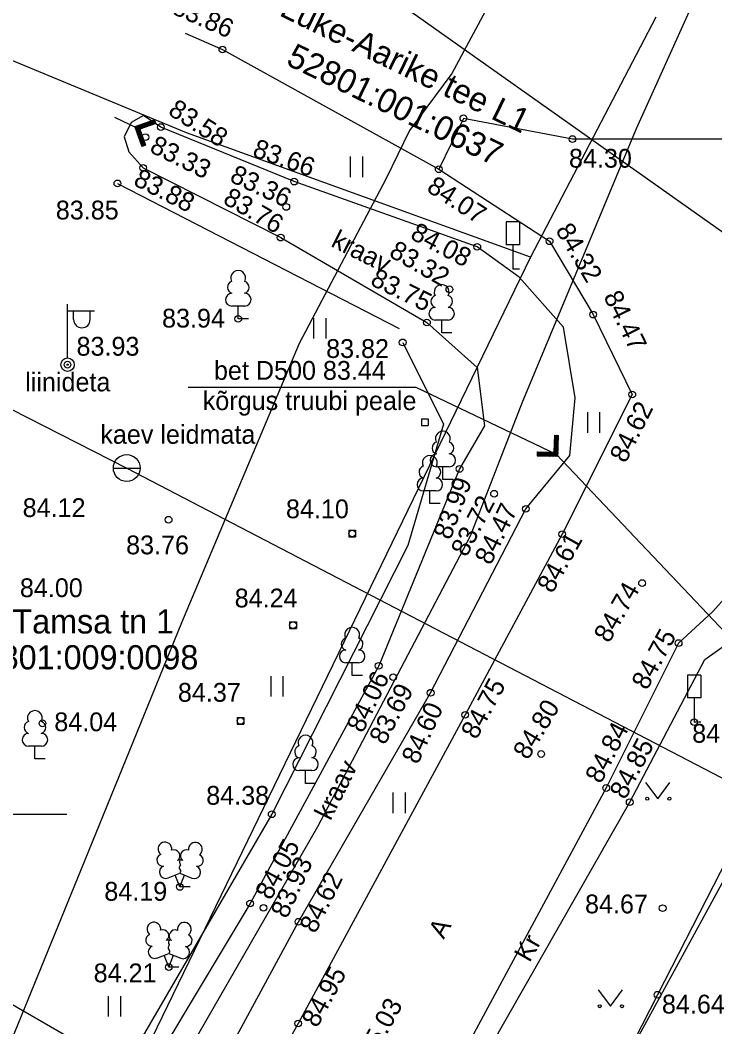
# Model space of a CAD drawing. Extents: x 648748 to 649126, y 6457789 to 6458252.
# Drawn here: x 648900.26 to 648926.14, y 6458192.08 to 6458229.55 of the extents above; entities that cross this region are included whole.
import ezdxf

# ---------------------------------------------------------------- set-up
doc = ezdxf.new("R2010")
doc.units = 0
for name, color, linetype in [('AED', 7, 'Continuous'), ('HALJASTUS', 7, 'Continuous'), ('KORGUS-EH2000', 7, 'Continuous'), ('LIIKLUS', 7, 'Continuous'), ('PIIR', 7, 'Continuous'), ('POST', 7, 'Continuous'), ('PUU', 7, 'Continuous'), ('SITRASS', 7, 'Continuous'), ('TEE', 7, 'Continuous'), ('TRUUP', 7, 'Continuous'), ('VEEKOGU', 7, 'Continuous'), ('VKAEV', 7, 'Continuous'), ('VORK', 7, 'Continuous'), ('VTRASS', 7, 'Continuous')]:
    doc.layers.add(name, color=color, linetype=linetype)

msp = doc.modelspace()

# ---------------------------------------------------------------- linework, layer by layer
at = {"layer": 'AED'}
for p, q in [((648915.208, 6458214.709), (648915.208, 6458214.459)), ((648915.208, 6458214.709), (648915.458, 6458214.709)), ((648915.208, 6458214.459), (648915.458, 6458214.459)), ((648915.458, 6458214.709), (648915.458, 6458214.459)), ((648912.5, 6458210.569), (648912.5, 6458210.319)), ((648912.5, 6458210.569), (648912.75, 6458210.569)), ((648912.5, 6458210.319), (648912.75, 6458210.319)), ((648912.75, 6458210.569), (648912.75, 6458210.319)), ((648910.297, 6458207.157), (648910.297, 6458206.907)), ((648910.297, 6458207.157), (648910.547, 6458207.157)), ((648910.547, 6458207.157), (648910.547, 6458206.907)), ((648910.297, 6458206.907), (648910.547, 6458206.907)), ((648908.343, 6458203.593), (648908.343, 6458203.343)), ((648908.343, 6458203.593), (648908.593, 6458203.593)), ((648908.593, 6458203.593), (648908.593, 6458203.343)), ((648908.343, 6458203.343), (648908.593, 6458203.343))]:
    msp.add_line(p, q, dxfattribs=at)
msp.add_lwpolyline([(648940.464, 6458193.018), (648933.165, 6458198.026), (648928.158, 6458201.393), (648924, 6458193.279), (648918.475, 6458182.472), (648914.302, 6458174.583), (648912.702, 6458171.37), (648918.536, 6458167.903)], dxfattribs=at)
at = {"layer": 'HALJASTUS'}
for p, q in [((648912.551, 6458224.472), (648912.551, 6458223.711)), ((648913.006, 6458224.472), (648913.006, 6458223.711)), ((648911.185, 6458218.458), (648911.185, 6458217.697)), ((648911.64, 6458218.458), (648911.64, 6458217.697)), ((648921.388, 6458214.956), (648921.388, 6458214.195)), ((648921.843, 6458214.956), (648921.843, 6458214.195)), ((648909.593, 6458205.137), (648909.593, 6458204.376)), ((648910.048, 6458205.137), (648910.048, 6458204.376)), ((648923.553, 6458201.182), (648924.016, 6458200.575)), ((648924.016, 6458200.575), (648924.462, 6458201.182)), ((648914.14, 6458200.802), (648914.14, 6458200.041)), ((648914.595, 6458200.802), (648914.595, 6458200.041)), ((648921.785, 6458193.457), (648922.248, 6458192.851)), ((648922.248, 6458192.851), (648922.694, 6458193.457)), ((648903.543, 6458193.224), (648903.543, 6458192.463)), ((648903.998, 6458193.224), (648903.998, 6458192.463))]:
    msp.add_line(p, q, dxfattribs=at)
msp.add_lwpolyline([(648914.508, 6458217.558), (648916.03, 6458214.515), (648914.704, 6458209.998), (648909.63, 6458199.994), (648897.923, 6458179.895)], dxfattribs=at)
for centre in [(648923.615, 6458200.575), (648924.444, 6458200.575), (648921.847, 6458192.851), (648922.676, 6458192.851)]:
    msp.add_circle(centre, 0.055, dxfattribs=at)
at = {"layer": 'KORGUS-EH2000'}
for centre in [(648907.793, 6458228.458), (648905.502, 6458225.572), (648916.77, 6458225.896), (648904.924, 6458225.198), (648920.831, 6458225.126), (648904.843, 6458224.054), (648915.851, 6458224.001), (648903.883, 6458223.474), (648910.47, 6458223.541), (648910.173, 6458222.6), (648909.964, 6458221.457), (648917.286, 6458221.114), (648919.979, 6458221.321), (648916.247, 6458219.532), (648908.384, 6458218.435), (648921.601, 6458218.591), (648915.412, 6458218.298), (648914.508, 6458217.558), (648902.026, 6458216.728), (648923.058, 6458215.616), (648916.627, 6458212.847), (648917.911, 6458211.924), (648919.095, 6458211.362), (648905.79, 6458210.957), (648912.625, 6458210.444), (648920.447, 6458210.418), (648923.423, 6458208.6), (648910.422, 6458207.032), (648924.786, 6458206.368), (648913.614, 6458205.518), (648914.152, 6458205.1), (648915.55, 6458204.519), (648908.468, 6458203.468), (648916.834, 6458203.698), (648901.093, 6458203.379), (648925.367, 6458203.425), (648919.666, 6458202.237), (648922.091, 6458200.973), (648922.963, 6458200.444), (648909.63, 6458199.994), (648906.207, 6458197.289), (648908.824, 6458196.674), (648909.326, 6458196.511), (648924.191, 6458196.5), (648910.629, 6458195.996), (648905.796, 6458194.307), (648924, 6458193.279), (648910.613, 6458192.21)]:
    msp.add_circle(centre, 0.125, dxfattribs=at)
at = {"layer": 'LIIKLUS'}
for points in [[(648918.364, 6458222.039), (648918.364, 6458221.189)], [(648918.864, 6458222.039), (648918.364, 6458222.039)], [(648918.864, 6458222.039), (648918.864, 6458221.189)], [(648918.864, 6458221.189), (648918.364, 6458221.189)], [(648918.614, 6458221.189), (648918.614, 6458220.289)], [(648918.864, 6458220.289), (648918.614, 6458220.289)], [(648925.117, 6458205.175), (648925.117, 6458204.325)], [(648925.617, 6458205.175), (648925.117, 6458205.175)], [(648925.617, 6458205.175), (648925.617, 6458204.325)], [(648925.617, 6458204.325), (648925.117, 6458204.325)], [(648925.367, 6458204.325), (648925.367, 6458203.425)], [(648925.617, 6458203.425), (648925.367, 6458203.425)]]:
    msp.add_lwpolyline(points, dxfattribs=at)
at = {"layer": 'PIIR'}
for p, q in [((648906.45, 6458225.36), (648896.582, 6458229.443)), ((648923.94, 6458229.66), (648919.27, 6458220.73)), ((648919.27, 6458220.73), (648906.45, 6458225.36)), ((648919.27, 6458220.73), (648904.5, 6458190.31)), ((648911.52, 6458170.14), (648929.78, 6458203.63)), ((648882.169, 6458203.173), (648904.5, 6458190.31))]:
    msp.add_line(p, q, dxfattribs=at)
at = {"layer": 'POST'}
for p, q in [((648902.026, 6458216.978), (648902.026, 6458218.978)), ((648902.026, 6458218.728), (648903.026, 6458218.728)), ((648902.252, 6458218.406), (648902.252, 6458218.728)), ((648902.865, 6458218.406), (648902.865, 6458218.728))]:
    msp.add_line(p, q, dxfattribs=at)
for radius in [0.25, 0.0234]:
    msp.add_circle((648902.026, 6458216.728), radius, dxfattribs=at)
msp.add_arc((648902.559, 6458218.406), 0.306, 180, 0, dxfattribs=at)
at = {"layer": 'PUU'}
for p, q in [((648903.883, 6458223.474), (648914.375, 6458218.079)), ((648908.624, 6458218.91), (648908.144, 6458218.91)), ((648908.384, 6458218.435), (648908.384, 6458218.91)), ((648908.764, 6458218.435), (648908.384, 6458218.435)), ((648916.201, 6458218.387), (648915.721, 6458218.387)), ((648915.961, 6458217.912), (648915.961, 6458218.387)), ((648916.341, 6458217.912), (648915.961, 6458217.912)), ((648916.245, 6458212.932), (648915.765, 6458212.932)), ((648916.005, 6458212.457), (648916.005, 6458212.932)), ((648916.385, 6458212.457), (648916.005, 6458212.457)), ((648915.76, 6458212.03), (648915.28, 6458212.03)), ((648915.52, 6458211.555), (648915.52, 6458212.03)), ((648915.9, 6458211.555), (648915.52, 6458211.555)), ((648912.865, 6458205.633), (648912.385, 6458205.633)), ((648912.625, 6458205.158), (648912.625, 6458205.633)), ((648913.005, 6458205.158), (648912.625, 6458205.158)), ((648901.051, 6458202.529), (648900.571, 6458202.529)), ((648900.811, 6458202.054), (648900.811, 6458202.529)), ((648901.191, 6458202.054), (648900.811, 6458202.054)), ((648911.128, 6458201.619), (648910.648, 6458201.619)), ((648910.888, 6458201.144), (648910.888, 6458201.619)), ((648911.268, 6458201.144), (648910.888, 6458201.144)), ((648905.767, 6458197.624), (648906.212, 6458197.799)), ((648906.207, 6458197.289), (648906.032, 6458197.729)), ((648906.207, 6458197.289), (648906.387, 6458197.729)), ((648906.212, 6458197.799), (648906.652, 6458197.619)), ((648906.587, 6458197.289), (648906.207, 6458197.289)), ((648905.356, 6458194.642), (648905.801, 6458194.817)), ((648905.796, 6458194.307), (648905.621, 6458194.747)), ((648905.796, 6458194.307), (648905.976, 6458194.747)), ((648905.801, 6458194.817), (648906.241, 6458194.637)), ((648906.176, 6458194.307), (648905.796, 6458194.307))]:
    msp.add_line(p, q, dxfattribs=at)
for points in [[(648906.212, 6458198.294), (648906.192, 6458198.219), (648906.192, 6458198.199), (648906.202, 6458198.169), (648906.222, 6458198.134), (648906.227, 6458198.114), (648906.212, 6458198.079), (648906.187, 6458198.029), (648906.182, 6458198.004), (648906.187, 6458197.989), (648906.197, 6458197.959), (648906.232, 6458197.899), (648906.237, 6458197.879), (648906.232, 6458197.859), (648906.217, 6458197.824), (648906.212, 6458197.799)], [(648905.801, 6458195.312), (648905.781, 6458195.237), (648905.781, 6458195.217), (648905.791, 6458195.187), (648905.811, 6458195.152), (648905.816, 6458195.132), (648905.801, 6458195.097), (648905.776, 6458195.047), (648905.771, 6458195.022), (648905.776, 6458195.007), (648905.786, 6458194.977), (648905.821, 6458194.917), (648905.826, 6458194.897), (648905.821, 6458194.877), (648905.806, 6458194.842), (648905.801, 6458194.817)]]:
    msp.add_lwpolyline(points, dxfattribs=at)
for centre, radius, start, end in [((648908.384, 6458219.955), 0.277, 332.58, 207.42), ((648908.214, 6458219.608), 0.233, 109.022, 253.142), ((648908.554, 6458219.608), 0.233, 286.851, 70.986), ((648915.961, 6458219.432), 0.277, 332.58, 207.42), ((648908.146, 6458219.148), 0.238, 90.002, 269.395), ((648908.621, 6458219.148), 0.238, 270.605, 89.998), ((648915.791, 6458219.084), 0.233, 109.022, 253.142), ((648916.131, 6458219.084), 0.233, 286.851, 70.986), ((648915.724, 6458218.624), 0.238, 90.002, 269.395), ((648916.199, 6458218.624), 0.238, 270.605, 89.998), ((648916.005, 6458213.977), 0.277, 332.58, 207.42), ((648915.835, 6458213.629), 0.233, 109.022, 253.142), ((648916.175, 6458213.629), 0.233, 286.851, 70.986), ((648915.52, 6458213.075), 0.277, 332.58, 207.42), ((648915.767, 6458213.169), 0.238, 90.002, 269.395), ((648916.242, 6458213.169), 0.238, 270.605, 89.998), ((648915.35, 6458212.727), 0.233, 109.022, 253.142), ((648915.69, 6458212.727), 0.233, 286.851, 70.986), ((648915.282, 6458212.267), 0.238, 90.002, 269.395), ((648915.757, 6458212.267), 0.238, 270.605, 89.998), ((648912.625, 6458206.678), 0.277, 332.58, 207.42), ((648912.455, 6458206.33), 0.233, 109.022, 253.142), ((648912.795, 6458206.33), 0.233, 286.851, 70.986), ((648912.388, 6458205.87), 0.238, 90.002, 269.395), ((648912.863, 6458205.87), 0.238, 270.605, 89.998), ((648900.811, 6458203.574), 0.277, 332.58, 207.42), ((648900.641, 6458203.226), 0.233, 109.022, 253.142), ((648900.981, 6458203.226), 0.233, 286.851, 70.986), ((648900.573, 6458202.766), 0.238, 90.002, 269.395), ((648901.048, 6458202.766), 0.238, 270.605, 89.998), ((648910.888, 6458202.664), 0.277, 332.58, 207.42), ((648910.718, 6458202.316), 0.233, 109.022, 253.142), ((648911.058, 6458202.316), 0.233, 286.851, 70.986), ((648910.651, 6458201.856), 0.238, 90.002, 269.395), ((648911.126, 6458201.856), 0.238, 270.605, 89.998), ((648905.65, 6458198.703), 0.256, 111.503, 232.517), ((648905.65, 6458198.703), 0.256, 350.486, 111.5), ((648906.786, 6458198.694), 0.256, 67.617, 188.631), ((648906.786, 6458198.694), 0.256, 306.6, 67.614), ((648905.576, 6458198.291), 0.224, 111.43, 274.499), ((648905.985, 6458198.452), 0.224, 308.504, 111.572), ((648906.448, 6458198.448), 0.225, 67.702, 230.513), ((648906.854, 6458198.282), 0.224, 264.618, 67.687), ((648905.681, 6458197.847), 0.237, 111.501, 291.5), ((648906.211, 6458198.056), 0.237, 66.766, 111.501), ((648906.742, 6458197.839), 0.238, 247.617, 67.616), ((648905.239, 6458195.721), 0.256, 111.503, 232.517), ((648905.239, 6458195.721), 0.256, 350.486, 111.5), ((648905.573, 6458195.471), 0.224, 308.504, 111.572), ((648906.036, 6458195.466), 0.225, 67.702, 230.513), ((648906.375, 6458195.713), 0.256, 67.617, 188.631), ((648906.375, 6458195.713), 0.256, 306.6, 67.614), ((648905.165, 6458195.31), 0.224, 111.43, 274.499), ((648905.8, 6458195.075), 0.237, 66.766, 111.501), ((648906.442, 6458195.3), 0.224, 264.618, 67.687), ((648905.269, 6458194.866), 0.237, 111.501, 291.5), ((648906.331, 6458194.858), 0.238, 247.617, 67.616)]:
    msp.add_arc(centre, radius, start, end, dxfattribs=at)
at = {"layer": 'SITRASS'}
for points in [[(648929.925, 6458240.085), (648929.233, 6458238.833), (648926.729, 6458233.327), (648923.21, 6458225.506), (648918.966, 6458215.361), (648917.027, 6458210.342), (648911.341, 6458199.533), (648902.157, 6458183.584), (648896.992, 6458174.764), (648890.118, 6458163.377), (648888.523, 6458160), (648880.878, 6458146.779), (648876.372, 6458138.998), (648873.186, 6458136.533), (648872.398, 6458135.159), (648870.194, 6458131.921), (648868.778, 6458129.583), (648863.975, 6458121.708)], [(648920.046, 6458238.741), (648918.974, 6458235.501), (648918.374, 6458231.362), (648916.343, 6458227.563), (648914.757, 6458225.445), (648913.89, 6458223.662), (648910.648, 6458217.515), (648906.266, 6458207.122), (648902.537, 6458197.956), (648897.439, 6458185.518), (648896.343, 6458186.017)]]:
    msp.add_lwpolyline(points, dxfattribs=at)
at = {"layer": 'TEE'}
for points in [[(648934.477, 6458237.848), (648927.903, 6458225.118), (648920.831, 6458225.126), (648916.77, 6458225.896), (648915.851, 6458224.001), (648919.979, 6458221.321), (648921.601, 6458218.591), (648923.058, 6458215.616), (648920.447, 6458210.418), (648916.834, 6458203.698), (648910.613, 6458192.21), (648903.667, 6458179.751)], [(648906.412, 6458229.067), (648907.793, 6458228.458), (648915.851, 6458224.001)], [(648891.319, 6458123.494), (648901.175, 6458127.077), (648933.887, 6458139.607), (648944.575, 6458143.741), (648947.822, 6458145.717), (648948.882, 6458147.636), (648949.478, 6458151.73), (648949.531, 6458156.617), (648950.372, 6458161.859), (648951.909, 6458167.68), (648954.505, 6458172.94), (648956.528, 6458180.218), (648952.525, 6458185.448), (648945.526, 6458192.898), (648938.29, 6458202.321), (648932.248, 6458208.399), (648929.676, 6458210.569), (648928.257, 6458209.969), (648926.047, 6458207.531), (648924.786, 6458206.368), (648922.091, 6458200.973), (648909.112, 6458176.906), (648898.467, 6458156.964), (648883.402, 6458130.595)], [(648902.496, 6458156.185), (648903.183, 6458160.572), (648904.191, 6458165.567), (648906.598, 6458170.127), (648910.322, 6458176.61), (648916.438, 6458188.99), (648922.963, 6458200.444), (648925.76, 6458205.755), (648928.587, 6458207.759), (648932.657, 6458207.561), (648933.376, 6458207.264)]]:
    msp.add_lwpolyline(points, dxfattribs=at)
at = {"layer": 'TRUUP'}
for p, q in [((648903.771, 6458225.943), (648904.627, 6458225.535)), ((648905.269, 6458225.839), (648904.536, 6458225.579)), ((648905.293, 6458225.771), (648904.627, 6458225.535)), ((648905.317, 6458225.704), (648904.717, 6458225.492)), ((648905.109, 6458225.631), (648904.795, 6458225.671)), ((648905.162, 6458225.649), (648904.848, 6458225.689)), ((648905.214, 6458225.668), (648904.9, 6458225.708)), ((648905.267, 6458225.686), (648904.953, 6458225.726)), ((648905.317, 6458225.705), (648905.005, 6458225.745)), ((648905.307, 6458225.731), (648905.057, 6458225.764)), ((648905.298, 6458225.758), (648905.11, 6458225.782)), ((648905.288, 6458225.785), (648905.162, 6458225.801)), ((648905.279, 6458225.811), (648905.214, 6458225.819)), ((648905.317, 6458225.704), (648905.269, 6458225.839)), ((648904.536, 6458225.579), (648904.795, 6458224.845)), ((648904.847, 6458225.538), (648904.536, 6458225.577)), ((648904.795, 6458225.519), (648904.546, 6458225.551)), ((648904.743, 6458225.501), (648904.555, 6458225.525)), ((648904.722, 6458225.478), (648904.564, 6458225.499)), ((648904.731, 6458225.452), (648904.574, 6458225.472)), ((648904.741, 6458225.425), (648904.583, 6458225.445)), ((648904.9, 6458225.557), (648904.586, 6458225.596)), ((648904.751, 6458225.399), (648904.592, 6458225.419)), ((648904.76, 6458225.373), (648904.601, 6458225.393)), ((648904.769, 6458225.346), (648904.611, 6458225.367)), ((648904.778, 6458225.32), (648904.62, 6458225.34)), ((648904.627, 6458225.535), (648904.863, 6458224.869)), ((648904.788, 6458225.293), (648904.63, 6458225.314)), ((648904.952, 6458225.575), (648904.639, 6458225.615)), ((648904.797, 6458225.267), (648904.639, 6458225.287)), ((648905.005, 6458225.594), (648904.691, 6458225.634)), ((648904.717, 6458225.492), (648904.93, 6458224.893)), ((648905.057, 6458225.612), (648904.743, 6458225.652)), ((648904.806, 6458225.241), (648904.648, 6458225.261)), ((648904.816, 6458225.215), (648904.658, 6458225.235)), ((648904.825, 6458225.188), (648904.667, 6458225.208)), ((648904.834, 6458225.161), (648904.676, 6458225.182)), ((648904.844, 6458225.135), (648904.686, 6458225.155)), ((648904.853, 6458225.109), (648904.695, 6458225.129)), ((648904.863, 6458225.083), (648904.704, 6458225.103)), ((648904.872, 6458225.056), (648904.713, 6458225.076)), ((648904.881, 6458225.029), (648904.723, 6458225.05)), ((648904.89, 6458225.003), (648904.732, 6458225.023)), ((648904.9, 6458224.977), (648904.741, 6458224.997)), ((648904.909, 6458224.951), (648904.751, 6458224.971)), ((648904.918, 6458224.924), (648904.76, 6458224.944)), ((648904.928, 6458224.898), (648904.77, 6458224.918)), ((648904.888, 6458224.878), (648904.779, 6458224.891)), ((648904.835, 6458224.859), (648904.788, 6458224.865)), ((648904.93, 6458224.893), (648904.795, 6458224.845)), ((648920.152, 6458213.466), (648920.169, 6458214.102)), ((648920.168, 6458214.097), (648920.309, 6458214.021)), ((648920.168, 6458214.069), (648920.309, 6458213.993)), ((648920.169, 6458214.102), (648920.311, 6458214.098)), ((648920.213, 6458214.101), (648920.31, 6458214.049)), ((648920.221, 6458213.394), (648920.24, 6458214.1)), ((648920.269, 6458214.1), (648920.311, 6458214.077)), ((648920.29, 6458213.321), (648920.311, 6458214.098)), ((648920.158, 6458213.705), (648920.299, 6458213.629)), ((648920.158, 6458213.677), (648920.298, 6458213.601)), ((648920.159, 6458213.733), (648920.3, 6458213.657)), ((648920.16, 6458213.761), (648920.3, 6458213.685)), ((648920.161, 6458213.817), (648920.302, 6458213.741)), ((648920.161, 6458213.789), (648920.301, 6458213.714)), ((648920.162, 6458213.845), (648920.302, 6458213.769)), ((648920.163, 6458213.901), (648920.304, 6458213.825)), ((648920.163, 6458213.873), (648920.303, 6458213.797)), ((648920.164, 6458213.929), (648920.305, 6458213.853)), ((648920.165, 6458213.957), (648920.305, 6458213.881)), ((648920.166, 6458213.985), (648920.306, 6458213.909)), ((648920.167, 6458214.041), (648920.307, 6458213.965)), ((648920.167, 6458214.013), (648920.307, 6458213.937)), ((648919.516, 6458213.484), (648919.512, 6458213.341)), ((648919.512, 6458213.341), (648920.29, 6458213.321)), ((648919.513, 6458213.371), (648919.571, 6458213.34)), ((648919.514, 6458213.412), (648920.221, 6458213.394)), ((648919.514, 6458213.398), (648919.626, 6458213.338)), ((648919.515, 6458213.455), (648919.737, 6458213.335)), ((648919.515, 6458213.426), (648919.682, 6458213.337)), ((648919.516, 6458213.484), (648920.152, 6458213.466)), ((648919.516, 6458213.482), (648919.793, 6458213.334)), ((648919.57, 6458213.482), (648919.849, 6458213.332)), ((648919.625, 6458213.48), (648919.904, 6458213.33)), ((648919.681, 6458213.479), (648919.96, 6458213.329)), ((648919.736, 6458213.477), (648920.015, 6458213.328)), ((648919.792, 6458213.476), (648920.071, 6458213.326)), ((648919.847, 6458213.475), (648920.126, 6458213.325)), ((648919.903, 6458213.473), (648920.181, 6458213.323)), ((648919.958, 6458213.472), (648920.237, 6458213.322)), ((648920.014, 6458213.47), (648920.291, 6458213.322)), ((648920.07, 6458213.469), (648920.291, 6458213.35)), ((648920.125, 6458213.467), (648920.292, 6458213.377)), ((648920.152, 6458213.481), (648920.293, 6458213.405)), ((648920.153, 6458213.509), (648920.293, 6458213.434)), ((648920.154, 6458213.565), (648920.295, 6458213.49)), ((648920.154, 6458213.537), (648920.294, 6458213.462)), ((648920.155, 6458213.593), (648920.296, 6458213.517)), ((648920.156, 6458213.621), (648920.296, 6458213.545)), ((648920.157, 6458213.649), (648920.297, 6458213.574)), ((648920.221, 6458213.394), (648927.912, 6458205.283))]:
    msp.add_line(p, q, dxfattribs=at)
msp.add_lwpolyline([(648906.523, 6458215.888), (648914.992, 6458215.888), (648920.221, 6458213.394)], dxfattribs=at)
at = {"layer": 'VEEKOGU'}
for points in [[(648904.849, 6458226), (648904.39, 6458225.741), (648904.128, 6458225.211), (648904.307, 6458224.65), (648904.843, 6458224.054), (648909.964, 6458221.457), (648915.412, 6458218.298), (648917.279, 6458216.617), (648917.551, 6458214.456), (648916.627, 6458212.847), (648913.614, 6458205.518), (648908.824, 6458196.674), (648903.68, 6458188.093)], [(648905.64, 6458186.776), (648910.629, 6458195.996), (648915.55, 6458204.519), (648919.095, 6458211.362), (648920.737, 6458213.353), (648920.926, 6458215.499), (648920.495, 6458218.12), (648918.846, 6458219.99), (648917.286, 6458221.114), (648910.47, 6458223.541), (648905.502, 6458225.572), (648904.849, 6458226)]]:
    msp.add_lwpolyline(points, dxfattribs=at)
at = {"layer": 'VKAEV'}
msp.add_line((648903.731, 6458212.879), (648904.731, 6458212.879), dxfattribs=at)
msp.add_circle((648904.231, 6458212.879), 0.5, dxfattribs=at)
at = {"layer": 'VORK'}
msp.add_line((648898, 6458200), (648902, 6458200), dxfattribs=at)
at = {"layer": 'VTRASS'}
for points in [[(648909.205, 6458232.372), (648914.854, 6458229.849), (648928.414, 6458220.256), (648945.257, 6458202.659), (648946.152, 6458201.5), (648950.981, 6458195.246), (648957.402, 6458181.131), (648957.363, 6458178.163), (648955.762, 6458171.425), (648951.333, 6458156.349), (648957.558, 6458132.798)], [(648896.188, 6458216.971), (648904.231, 6458212.879)], [(648904.231, 6458212.879), (648940.565, 6458193.977), (648965.109, 6458166.027), (648997.904, 6458167.882), (649020.691, 6458169.172)]]:
    msp.add_lwpolyline(points, dxfattribs=at)

# ---------------------------------------------------------------- texts
at = {"layer": 'KORGUS-EH2000'}
for s, rotation, p in [('83.86', 336.2167, (648905.868, 6458229.81)), ('83.58', 327.1169, (648905.73, 6458226.066)), ('83.33', 333.5532, (648905.041, 6458224.665)), ('83.66', 340.4012, (648908.875, 6458224.494)), ('84.30', 359.9409, (648920.701, 6458224.062)), ('83.88', 333.1056, (648904.436, 6458223.434)), ('83.36', 334.7257, (648908.024, 6458223.564)), ('84.07', 327.0094, (648915.359, 6458223.209)), ('83.76', 329.8982, (648907.772, 6458222.755)), ('84.08', 332.049, (648914.749, 6458221.438)), ('84.32', 300.7063, (648920.183, 6458221.734)), ('83.32', 330.0724, (648913.956, 6458220.78)), ('83.75', 333.9144, (648913.261, 6458219.713)), ('84.47', 296.094, (648921.973, 6458219.272)), ('84.62', 63.327, (648922.808, 6458213.03)), ('83.99', 69.6638, (648916.284, 6458210.174)), ('83.72', 62.628, (648916.885, 6458209.534)), ('84.47', 64.0634, (648917.783, 6458209.232)), ('84.61', 60.7388, (648920.084, 6458208.182)), ('84.74', 60.2551, (648922.194, 6458206.335)), ('84.75', 61.5571, (648923.607, 6458204.581)), ('84.06', 64.408, (648913.018, 6458202.984)), ('84.75', 61.7355, (648917.257, 6458202.742)), ('83.69', 62.231, (648913.841, 6458202.542)), ('84.60', 65.7029, (648915.072, 6458201.818)), ('84.80', 58.8287, (648919.171, 6458201.982)), ('84.84', 63.1344, (648921.892, 6458201.099)), ('84.85', 62.2289, (648922.798, 6458200.507)), ('84.05', 61.7155, (648909.59, 6458196.764)), ('83.93', 65.2826, (648910.196, 6458196.078)), ('84.62', 63.6037, (648911.257, 6458195.522)), ('84.95', 61.5633, (648911.32, 6458192.016)), ('85.03', 61.5633, (648913.413, 6458190.843))]:
    msp.add_text(s, height=0.7, rotation=rotation, dxfattribs=at).set_placement(p)
for s, p in [('83.85', (648901.588, 6458222.133)), ('83.94', (648905.545, 6458218.109)), ('83.93', (648902.36, 6458217.062)), ('83.82', (648911.656, 6458216.978)), ('84.12', (648900.353, 6458211.058)), ('84.10', (648910.16, 6458211.012)), ('83.76', (648904.206, 6458209.67)), ('84.00', (648900.251, 6458208.076)), ('84.24', (648908.25, 6458207.693)), ('84.37', (648906.136, 6458204.183)), ('84.04', (648901.532, 6458203.085)), ('84.89', (648925.291, 6458202.658)), ('84.38', (648907.191, 6458200.349)), ('84.19', (648903.395, 6458196.776)), ('84.67', (648921.299, 6458196.307)), ('84.21', (648902.997, 6458193.741)), ('84.64', (648924.164, 6458192.579))]:
    msp.add_text(s, height=0.7, dxfattribs=at).set_placement(p)
at = {"layer": 'PIIR'}
for s, rotation, p in [('Luke-Aarike tee L1', 334.0385, (648909.871, 6458229.742)), ('52801:001:0637', 334.0385, (648910.122, 6458227.912)), ('Tamsa tn 1', 0, (648899.972, 6458206.723)), ('52801:009:0098', 0, (648898.197, 6458205.388))]:
    msp.add_text(s, height=0.9, rotation=rotation, dxfattribs=at).set_placement(p)
at = {"layer": 'POST'}
msp.add_text('liinideta', height=0.7, dxfattribs=at).set_placement((648900.447, 6458215.734))
at = {"layer": 'TEE'}
for s, rotation, p in [('A', 60.2687, (648916.034, 6458195.319)), ('Kr', 60.3302, (648919.23, 6458194.449))]:
    msp.add_text(s, height=0.7, rotation=rotation, dxfattribs=at).set_placement(p)
at = {"layer": 'TRUUP'}
for s, p in [('bet D500 83.44', (648907.479, 6458216.166)), ('kõrgus truubi peale', (648907.06, 6458215.038))]:
    msp.add_text(s, height=0.7, dxfattribs=at).set_placement(p)
at = {"layer": 'VEEKOGU'}
for rotation, p in [(333.2901, (648911.797, 6458221.148)), (63.3854, (648911.819, 6458199.728))]:
    msp.add_text('kraav', height=0.7, rotation=rotation, dxfattribs=at).set_placement(p)
at = {"layer": 'VKAEV'}
msp.add_text('kaev leidmata', height=0.7, dxfattribs=at).set_placement((648903.246, 6458213.785))

doc.saveas('drawing.dxf')
